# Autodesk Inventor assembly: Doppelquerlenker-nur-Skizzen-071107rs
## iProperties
Created: 2007-11
Part Number: Doppelquerlenker-nur-Skizzen-071107rs
Project: 11308
Document SubType Name: Assembly
Designer: rsc
Engineer: Dr.-Ing. Roland Schröder
Manager: Dr.-Ing. Roland Schröder
Company: www.Das-Entwicklungsbuero.de
Author: rsc
Oberflächen: Ra 3,2
Toleranzen: ISO 2768 - m
a: 17.000 oE
b: 10.000 mm
d: 34.000 mm
